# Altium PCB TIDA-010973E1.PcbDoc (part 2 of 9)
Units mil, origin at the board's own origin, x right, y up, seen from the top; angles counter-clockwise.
Board outline 5166 x 3669 mil, 8 copper layers (L01 - TOP, L02 - GND, L03 - SIG, L04 - GND, L05 - PWR, L06 - SIG, L07 - GND, L08 - BOTTOM), stack 61.7 mil thick; 677 components, 493 nets, 2522 pads, 1424 vias.
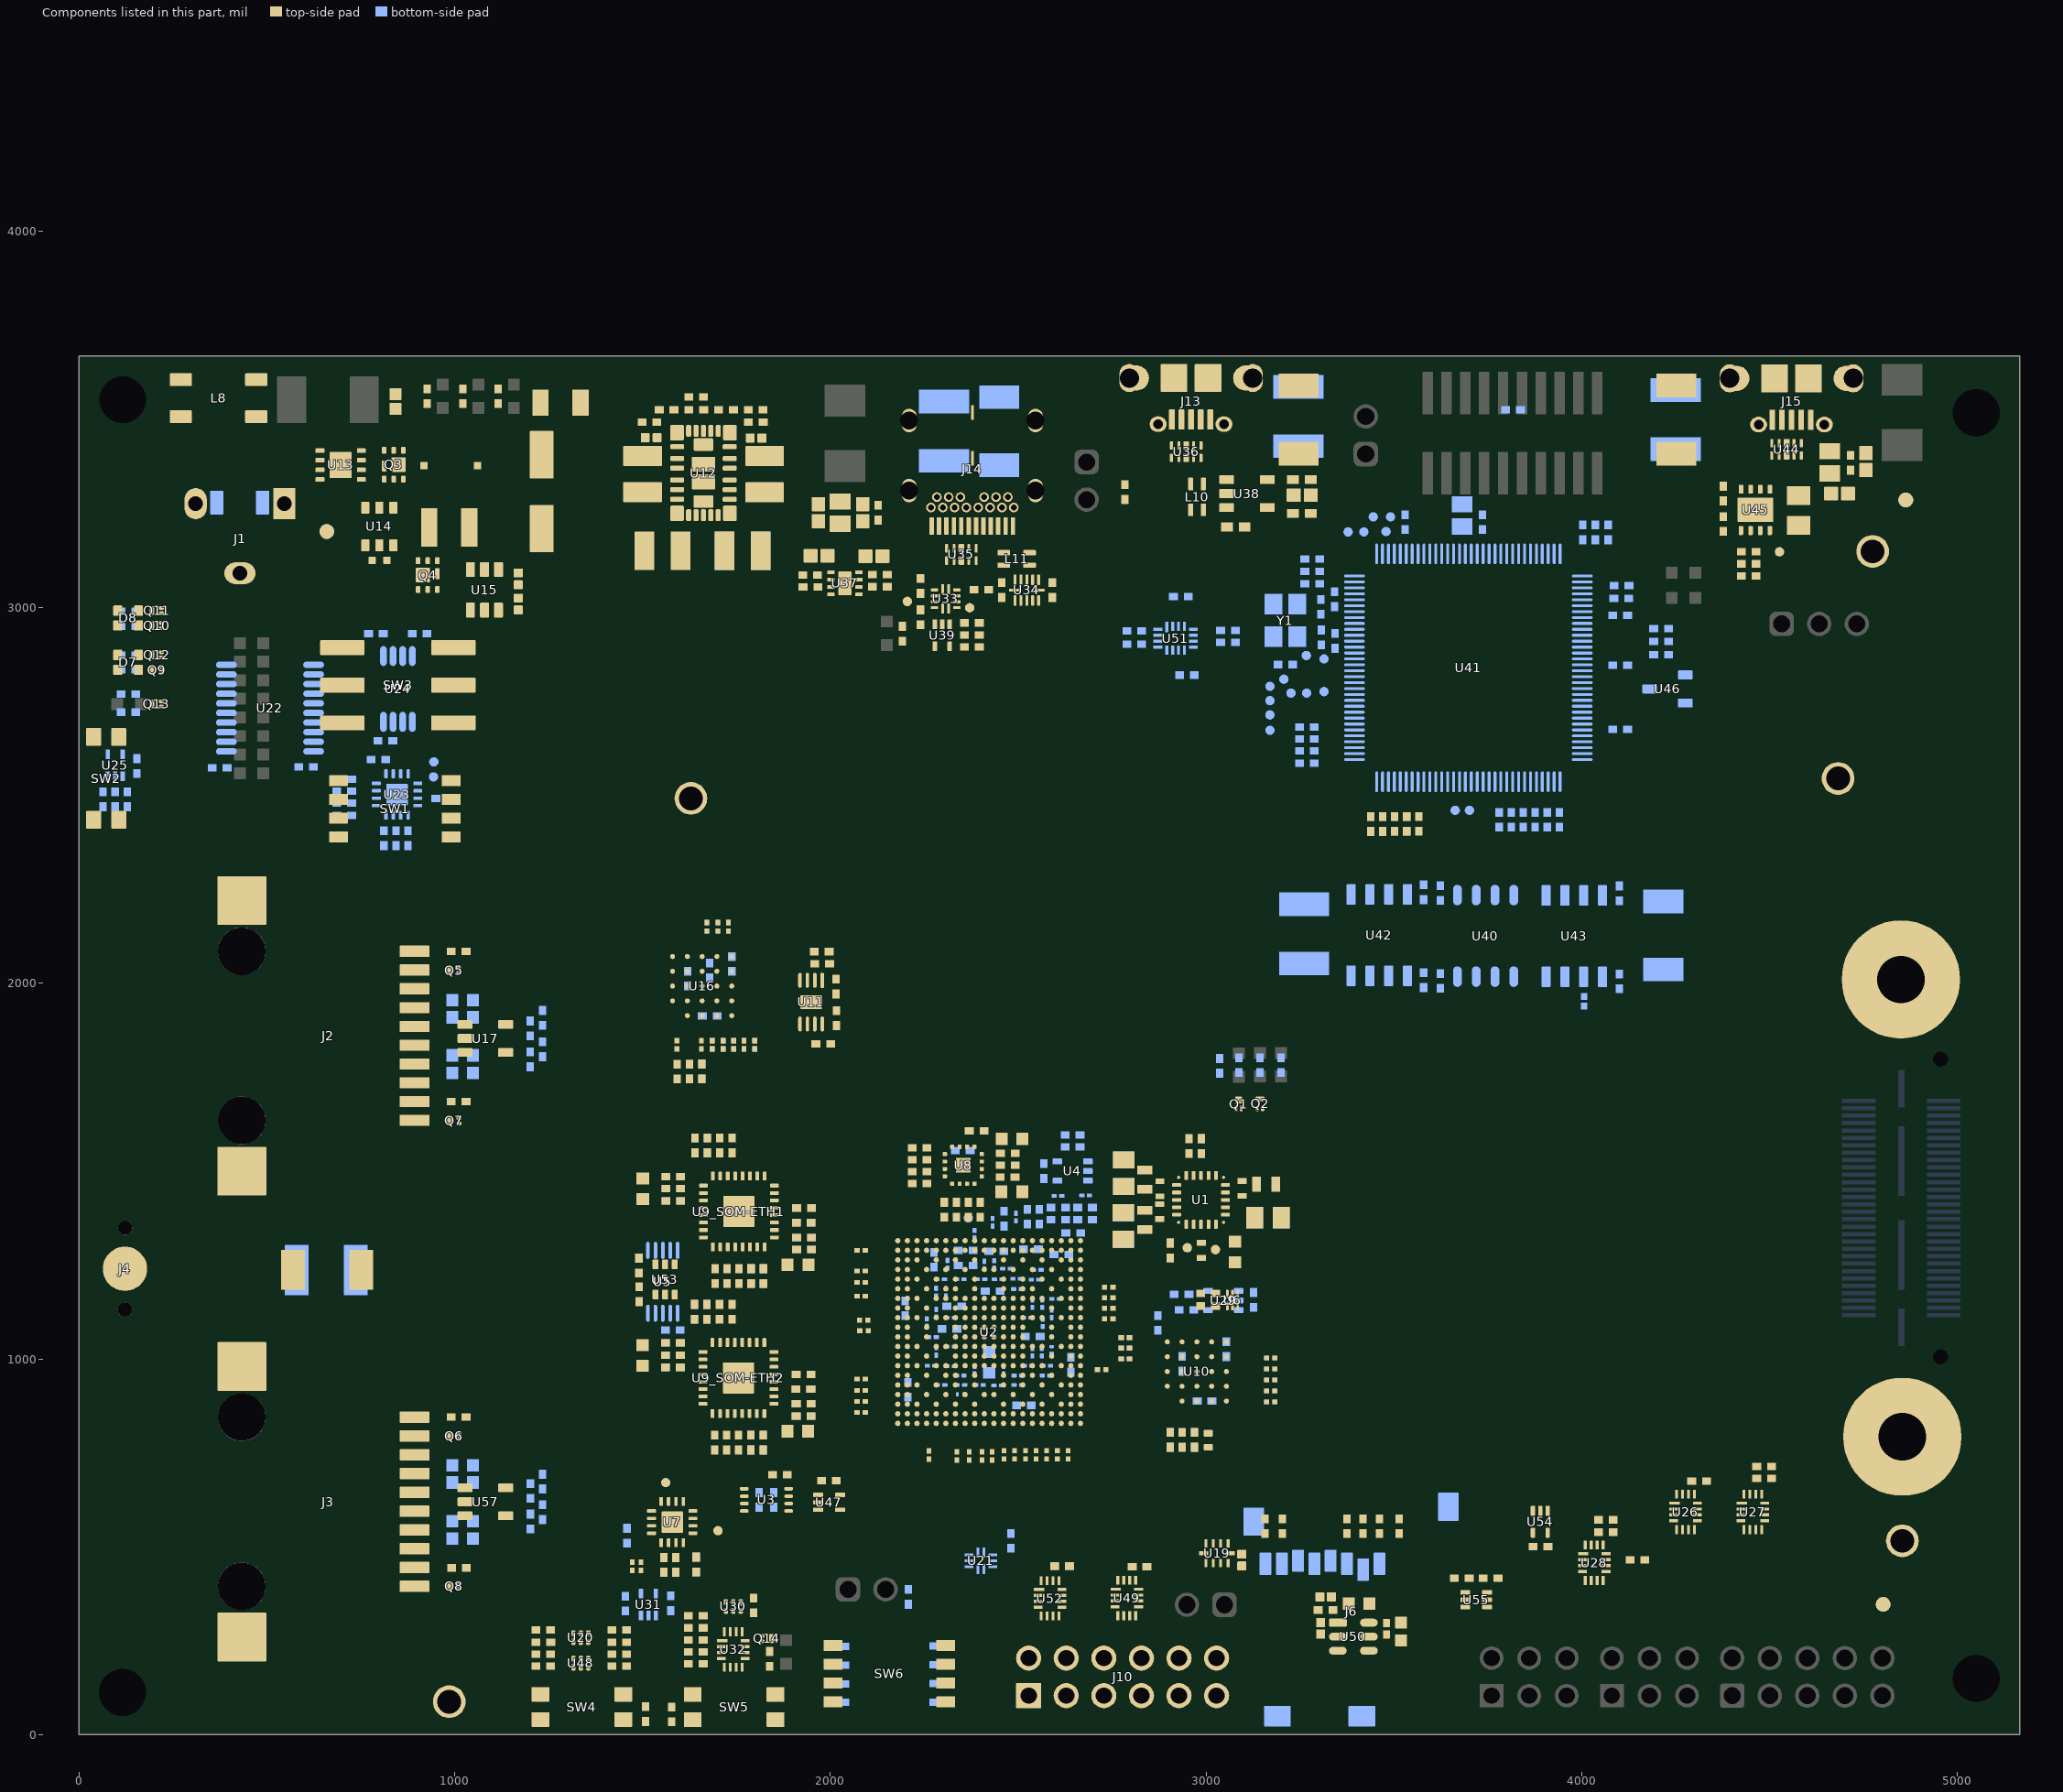
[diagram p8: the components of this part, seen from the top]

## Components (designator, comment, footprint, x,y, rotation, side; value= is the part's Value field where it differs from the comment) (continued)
L3 "74479262147" WE-PMCI_0603LP 2837.13,1477.54 r90 top value=470nH
L4_SOM-ETH1 "742792604" 0603L 1914.13,1250.64 r0 top value="22 ohm" (schematic designator L4)
L4_SOM-ETH2 "742792604" 0603L 1913.13,807.64 r0 top value="22 ohm" (schematic designator L4)
L5_SOM-ETH1 "742792604" 0603L 1501.26,1452.65 r90 top value="22 ohm" (schematic designator L5)
L5_SOM-ETH2 "742792604" 0603L 1500.26,1009.65 r90 top value="22 ohm" (schematic designator L5)
L6 "744031002" WE-TPC-S 990,3377 r0 top value=2.5uH
L7 "742792113" 1206L 1282,3545 r0 top value="120 ohm"
L8 "744212331" FP-744212331_SMT_CMC_6MM5_3MM6-MFG 372,3557 r0 top
L9 "74279206" 0805L 2026.32,3252 r270 top value="30 ohm"
L10 "744233900" FP-744233900_SMT4-MFG 2976,3294 r270 top
L11 "744233900" FP-744233900_SMT4-MFG 2496,3129 r0 top
L12 "74279206" 0805L 4660,3386 r90 top value="30 ohm"
L13 "74279271" 0402L 2442,1287 r0 bottom value="120 ohm"
L14 "74279271" 0402L 2606.68,1371 r0 bottom value="120 ohm"
L15 "74279271" 0402L 2678,1371 r180 bottom value="120 ohm"
L16 "74279266" 0603L 3407,349 r0 top value="1000 ohm"
L17 "742792604" 0603L 2484.02,1585.91 r180 top value="22 ohm"
L18 "742792604" 0603L 2483.04,1445.17 r180 top value="22 ohm"
LBL1 "THT-14-423-10" Label_650x200 4900,2571 r90 top
Logo1 "Texas Instruments" TI_Stacked_Overlay_Small 2537,2027 r0 top
Logo2 "CE Mark" CE_Mark_5mm 4507,905 r0 top
Logo3 "FCC disclaimer" FCC_disclaimer 5096,2357 r90 top
Logo4 "WEEE logo" WEEE_Minimum 5029,3267 r0 top
MH1 "MTG_NoPads" NPTH125mil 117,3553 r0 top
MH2 "MTG_NoPads" NPTH125mil 116,113 r0 top
MH3 "MTG_NoPads" NPTH125mil 5050,3518 r0 top
MH4 "MTG_NoPads" NPTH125mil 5050,150 r0 top
Q1 "BC847BFA-7B" FP-BC847BFA-7B_DFN3-MFG 3086.5,1679 r0 top value=45V
Q2 "CSD13383F4" YJC0003A 3143.5,1679 r90 top value=12V
Q3 "CSD19538Q2" DQK0006C 838.2,3380 r270 top value=100V
Q4 "CSD19538Q2" DQK0006C 928.8,3086 r90 top value=100V
Q5 "CSD13383F4" YJC0003A 998.23,2034 r180 top value=12V
Q6 "CSD13383F4" YJC0003A 998.23,795 r180 top value=12V
Q7 "CSD13383F4" YJC0003A 999,1634 r180 top value=12V
Q8 "CSD13383F4" YJC0003A 998.23,395 r180 top value=12V
Q9 "CSD13383F4" YJC0003A 207.21,2833.69 r180 top value=12V
Q10 "CSD13383F4" YJC0003A 207.21,2951.69 r180 top value=12V
Q11 "CSD13383F4" YJC0003A 207.21,2991.69 r180 top value=12V
Q12 "CSD13383F4" YJC0003A 207.21,2873.69 r180 top value=12V
Q13 "CSD13383F4" YJC0003A 207,2743 r180 top value=12V
Q14 "CSD13383F4" YJC0003A 1831,256 r0 top value=12V
R1 "CRCW040210K0FKED" 0402L 2556.15,1378.48 r90 bottom value=10.0k
R2 "CRCW04022K67FKED" 0402L 2524.15,1378.48 r270 bottom value=2.67k
R3 "CRCW0402180RJNED" 0402L 3200,1782 r90 bottom value=180
R4 "CRCW0402180RJNED" 0402L 3087,1782 r270 bottom value=180
R5 "CRCW0402180RJNED" 0402L 3143.5,1782 r270 bottom value=180
R6 "CRCW040210K0FKED" 0402L 1810.44,625 r270 bottom value=10.0k
R7 "CRCW040210K0FKED" 0402L 3005.68,1141 r180 top value=10.0k
R8 "CRCW040210K0FKED" 0402L 3126,1157 r270 bottom value=10.0k
R9 "CRCW040210K0FKED" 0402L 2645,1596 r180 bottom value=10.0k
R10 "CRCW040210K0FKED" 0402L 2568,1500 r270 bottom value=10.0k
R11 "CRCW04021K00FKED" 0402L 3036.5,1780 r90 bottom value=1.00k
R12 "CRCW040210K0FKED" 0402L 96.81,2489.22 r270 bottom value=10.0k
R13 "RC0201FR-074K7L" 0201L 2431,742 r270 top value=4.70k
R14 "CRCW040210K0FKED" 0402L 1849.81,625 r90 bottom value=10.0k
R15 "CRCW040210K0FKED" 0402L 1643,453 r90 top value=10.0k
R16 "CRCW020110K0FKED" 0201L 2741,1163 r180 top value=10.0k
R17 "RC0201FR-074K7L" 0201L 1496,448 r270 top value=4.70k
R18 "RMCF0402FT33R0" 0402L 2237.43,1466.72 r180 top value=33.0
R19 "RMCF0402FT33R0" 0402L 2237.43,1498.72 r180 top value=33.0
R20 "RMCF0402FT33R0" 0402L 2399.23,1397.18 r270 top value=33.0
R21 "CRCW040210K0FKED" 0402L 2352.37,1554.91 r0 bottom value=10.0k
R22 "CRCW04020000Z0ED" 0402L 2389.37,1606.91 r180 top value=0
R23_SOM-ETH1 "CRCW04022K20FKED" 0402L 1725.13,1220.64 r90 top value=2.20k (schematic designator R23)
R23_SOM-ETH2 "CRCW04022K20FKED" 0402L 1724.13,777.64 r90 top value=2.20k (schematic designator R23)
R24_SOM-ETH1 "CRCW040210K0FKED" 0402L 1640.13,1568.45 r270 top value=10.0k (schematic designator R24)
R24_SOM-ETH2 "CRCW040210K0FKED" 0402L 1639.13,1125.45 r270 top value=10.0k (schematic designator R24)
R25_SOM-ETH1 "CRCW040210K0FKED" 0402L 1640.13,1568.45 r270 bottom value=10.0k (schematic designator R25)
R25_SOM-ETH2 "CRCW040210K0FKED" 0402L 1639.13,1125.45 r270 bottom value=10.0k (schematic designator R25)
R26_SOM-ETH1 "CRCW04026K49FKED" 0402L 1693.13,1220.64 r90 top value=6.49k (schematic designator R26)
R26_SOM-ETH2 "CRCW04026K49FKED" 0402L 1692.13,777.64 r90 top value=6.49k (schematic designator R26)
R27_SOM-ETH1 "CRCW040210K0FKED" 0402L 1930.13,1401.64 r180 top value=10.0k (schematic designator R27)
R27_SOM-ETH2 "CRCW040210K0FKED" 0402L 1929.13,958.64 r180 top value=10.0k (schematic designator R27)
R28_SOM-ETH1 "CRCW04021K50FKED" 0402L 1673.13,1568.45 r90 bottom value=1.50k (schematic designator R28)
R28_SOM-ETH2 "CRCW04021K50FKED" 0402L 1672.13,1125.45 r90 bottom value=1.50k (schematic designator R28)
R29_SOM-ETH1 "CRCW04022K49FKED" 0402L 1706.13,1568.45 r270 top value=2.49k (schematic designator R29)
R29_SOM-ETH2 "CRCW04022K49FKED" 0402L 1705.13,1125.45 r270 top value=2.49k (schematic designator R29)
R30_SOM-ETH1 "CRCW04022K49FKED" 0402L 1739.13,1568.45 r270 top value=2.49k (schematic designator R30)
R30_SOM-ETH2 "CRCW04022K49FKED" 0402L 1738.13,1125.45 r270 top value=2.49k (schematic designator R30)
R31_SOM-ETH1 "CRCW04022K49FKED" 0402L 1789.13,1220.64 r90 top value=2.49k (schematic designator R31)
R31_SOM-ETH2 "CRCW04022K49FKED" 0402L 1788.13,777.64 r90 top value=2.49k (schematic designator R31)
R32_SOM-ETH1 "CRCW04022K49FKED" 0402L 1822.13,1220.64 r90 top value=2.49k (schematic designator R32)
R32_SOM-ETH2 "CRCW04022K49FKED" 0402L 1821.13,777.64 r90 top value=2.49k (schematic designator R32)
R33 "CRCW040210K0FKED" 0402L 2969.13,784.64 r270 top value=10.0k
R34 "CRCW040210K0FKED" 0402L 2936.8,784.64 r270 top value=10.0k
R35 "CRCW040210K0FKED" 0402L 2872,1096 r90 bottom value=10.0k
R36 "CRCW040210K0FKED" 0402L 2904.47,784.64 r270 top value=10.0k
R37 "RC0201FR-0749K9L" 0201L 3172.11,1002.64 r180 bottom value=49.9k
R38 "RC0201FR-0749K9L" 0201L 3172.11,914.89 r180 bottom value=49.9k
R39 "CRCW02014K70FKED" 0201_033L 2785,1000 r0 bottom value=4.70k
R40 "RC0201FR-0749K9L" 0201L 2784.98,1029 r0 bottom value=49.9k
R41 "RC0201FR-0749K9L" 0201L 2785,1057 r0 bottom value=49.9k
R42 "RC0201FR-0749K9L" 0201L 3172.11,973.39 r180 bottom value=49.9k
R43 "RC0201FR-0749K9L" 0201L 3172.11,944.14 r180 bottom value=49.9k
R44 "RC0201FR-0749K9L" 0201L 3172.11,885.64 r180 bottom value=49.9k
R45 "RC0201JR-0722RL" 0201L 3172.11,1002.64 r0 top value=22
R46 "RC0201JR-0722RL" 0201L 3172.11,914.89 r0 top value=22
R47 "RC0201JR-0722RL" 0201L 2785,1000 r180 top value=22
R48 "RC0201JR-0722RL" 0201L 2784.98,1029 r180 top value=22
R49 "RC0201JR-0722RL" 0201L 2785,1057 r180 top value=22
R50 "RC0201JR-0722RL" 0201L 3172.11,973.39 r0 top value=22
R51 "CRCW04021K00FKED" 0402L 2969.13,784.64 r90 bottom value=1.00k
R52 "CRCW0402100KFKED" 0402L 2904.47,784.64 r90 bottom value=100k
R53 "RC0201JR-0722RL" 0201L 3172.11,944.14 r0 top value=22
R54 "RC0201JR-0722RL" 0201L 3172.11,885.64 r0 top value=22
R55 "CRCW040210K0FKED" 0402L 2015.32,1991 r270 top value=10.0k
R56 "CRCW040210K0FKED" 0402L 1978.32,2052 r180 top value=10.0k
R57 "CRCW040210K0FKED" 0402L 1977.32,2084 r180 top value=10.0k
R58 "CRCW0402100KFKED" 0402L 1801.72,3492.65 r180 top value=100k
R59 "CRCW040235K7FKED" 0402L 1801.41,3525.65 r0 top value=35.7k
R60 "CRCW040240K2FKED" 0402L 1564.41,3525.65 r180 top value=40.2k
R61 "CRCW040213K0FKED" 0402L 1518.72,3492.65 r0 top value=13.0k
R62 "CRCW040210K0DHEDP" 0402L 1643.41,3525.65 r180 top value=10.0k
R63 "CRCW0402750RFKED" 0402L 1022,3562 r270 top value=750
R64 "CRCW04021K00FKED" 0402L 927,3562 r270 top value=1.00k
R65 "CRCW0402750RFKED" 0402L 1116,3562 r270 top value=750
R66 "RC0201FR-0749K9L" 0201L 1743,1836.02 r90 bottom value=49.9k
R67 "RC0201FR-0749K9L" 0201L 1685.67,1836 r90 bottom value=49.9k
R68 "CRCW02014K70FKED" 0201_033L 1672,2150 r270 bottom value=4.70k
R69 "RC0201FR-0749K9L" 0201L 1729,2150 r270 bottom value=49.9k
R70 "RC0201FR-0749K9L" 0201L 1700.5,2150 r270 bottom value=49.9k
R71 "RC0201FR-0749K9L" 0201L 1799,1836 r90 bottom value=49.9k
R72 "RC0201FR-0749K9L" 0201L 1770.67,1836 r90 bottom value=49.9k
R73 "RC0201FR-0749K9L" 0201L 1715,1836 r90 bottom value=49.9k
R74 "RC0201JR-0722RL" 0201L 1743,1836.02 r90 top value=22
R75 "RC0201JR-0722RL" 0201L 1685.67,1836 r90 top value=22
R76 "RC0201JR-0722RL" 0201L 1672,2150 r270 top value=22
R77 "RC0201JR-0722RL" 0201L 1729,2150 r270 top value=22
R78 "RC0201JR-0722RL" 0201L 1700.5,2150 r270 top value=22
R79 "RC0201JR-0722RL" 0201L 1799,1836 r90 top value=22
R80 "RC0201JR-0722RL" 0201L 1770.67,1836 r90 top value=22
R81 "RC0201JR-0722RL" 0201L 1715,1836 r90 top value=22
R82 "RC0201JR-0722RL" 0201L 1657.33,1836 r90 top value=22
R83 "CRCW02010000Z0ED" 0201L 1592,1836 r90 top value=0
R84 "CRCW0402220RJNTD" 0402L 1011,2085 r0 top value=220
R85 "CRCW0402220RJNTD" 0402L 1011,845 r0 top value=220
R86 "CRCW0402220RJNTD" 0402L 1011,1685 r0 top value=220
R87 "CRCW0402220RJNTD" 0402L 1012,444 r0 top value=220
R88 "CRCW20101M00FKEF" 2010 661,1237.68 r180 top value=1.00Meg
R89 "CRCW0402180RJNED" 0402L 132,2768.94 r0 bottom value=180
R90 "CRCW0402220RJNTD" 0402L 132,2950 r180 bottom value=220
R91 "CRCW0402180RJNED" 0402L 132,2990 r180 bottom value=180
R92 "CRCW0402220RJNTD" 0402L 132,2834 r180 bottom value=220
R93 "CRCW040210K0FKED" 0402L 2208,367 r90 bottom value=10.0k
R94 "CRCW0402180RJNED" 0402L 132,2873.37 r180 bottom value=180
R95 "CRCW040210K0FKED" 0402L 719,2695 r180 bottom value=10.0k
R96 "CRCW04022K67FKED" 0402L 375,2573 r0 bottom value=2.67k (schematic designator R?)
R98 "CRCW0402100RFKED" 0402L 64.81,2489.22 r90 bottom value=100
R99 "CRCW040210K0FKED" 0402L 1459,529.68 r90 bottom value=10.0k
R100 "CRCW040210K0FKED" 0402L 1643,453 r90 bottom value=10.0k
R103 "CRCW040210K0FKED" 0402L 812,2386 r90 bottom value=10.0k
R105 "CRCW040210K0FKED" 0402L 970,2492 r180 bottom value=10.0k
R107 "CRCW040210K0FKED" 0402L 706.31,2447 r0 bottom value=10.0k
R108 "CRCW0402100KFKED" 0402L 706.32,2479 r180 bottom value=100k
R109 "CRCW0402100KFKED" 0402L 706.32,2511 r180 bottom value=100k
R110 "CRCW0402100KFKED" 0402L 706.32,2543 r180 bottom value=100k
R111 "CRCW0402100KFKED" 0402L 797.32,2595 r180 bottom value=100k
R112 "CRCW0402100RFKED" 0402L 1508,55 r90 top value=100
R113 "CRCW0402100RFKED" 0402L 1578,54 r90 top value=100
R114 "CRCW040210K0FKED" 0402L 705,2891 r0 bottom value=10.0k
R115 "CRCW040210K0FKED" 0402L 996,2693 r180 bottom value=10.0k
R116 "CRCW040210K0FKED" 0402L 816,2645 r0 bottom value=10.0k
R117 "CRCW040210K0FKED" 0402L 790.68,2930 r0 bottom value=10.0k
R118 "CRCW040210K0FKED" 0402L 4485,714 r180 top value=10.0k
R119 "CRCW040210K0FKED" 0402L 4064,572 r180 top value=10.0k
R120 "CRCW020110K0FKED" 0201L 2741,1191 r180 top value=10.0k
R121 "CRCW020110K0FKED" 0201L 2337,742 r90 top value=10.0k
R122 "CRCW040249R9FKED" 0402L 1642.24,316.46 r0 top value=49.9
R123 "CRCW020110K0FKED" 0201L 2370,742 r90 top value=10.0k
R124 "CRCW040210K0FKED" 0402L 2018.78,235 r0 bottom value=10.0k
R125 "CRCW040210K0FKED" 0402L 2018.78,185.33 r0 bottom value=10.0k
R126 "CRCW040210K0FKED" 0402L 2018.78,135.67 r0 bottom value=10.0k
R127 "CRCW040210K0FKED" 0402L 2018.78,86 r0 bottom value=10.0k
R128 "CRCW04021K00FKED" 0402L 2295,236 r0 bottom value=1.00k
R129 "CRCW04021K00FKED" 0402L 2295,186 r0 bottom value=1.00k
R130 "CRCW04021K00FKED" 0402L 2295,136 r0 bottom value=1.00k
R131 "CRCW04021K00FKED" 0402L 2295,86 r0 bottom value=1.00k
R132 "CRCW0402110KFKED" 0402L 2784,3307 r270 top value=110k
R133 "CRCW040210K0FKED" 0402L 2456,3046 r90 top value=10.0k
R134 "CRCW040210K0FKED" 0402L 2591,3046 r90 top value=10.0k
R135 "CRCW0402200KFKED" 0402L 2240,2974 r270 top value=200k
R136 "CRCW040210K0FKED" 0402L 2377,2958.81 r0 top value=10.0k
R137 "CRCW040210K0FKED" 0402L 2377,2926.81 r0 top value=10.0k
R138 "CRCW0402909KFKED" 0402L 2240,3057 r90 top value=909k
R139 "CRCW20101M00FKEF" 2010 3246.32,3500 r90 top value=1.00Meg
R140 "CRCW040210K0FKED" 0402L 1947.33,3054.28 r0 top value=10.0k
R141 "CRCW040210K0FKED" 0402 3079,3214 r180 top value=10.0k
R142 "CRCW040210K0FKED" 0402 3255,3250 r0 top value=10.0k
R143 "CRCW0402715RFKED" 0402L 2192.28,2930 r90 top value=715
R144 "CRCW20101M00FKEF" 2010 2450,3469 r270 bottom value=1.00Meg
R145 "CRCW04020000Z0ED" 0402L 3282.67,3063.35 r180 bottom value=0
R146 "CRCW0402100RFKED" 0402L 3282.67,3095.85 r180 bottom value=100
R147 "CRCW0402330KFKED" 0402L 4070,3199.69 r90 bottom value=330k
R148 "CRCW0402330KFKED" 0402L 4036,3199.69 r270 bottom value=330k
R149 "CRCW0402360RJNED" 0402L 4105,3024 r180 bottom value=360
R150 "CRCW0402360RJNED" 0402L 4105.69,3058 r180 bottom value=360
R151 "CRCW04021K00FKED" 0402L 3812,2435 r90 bottom value=1.00k
R152 "CRCW04021K00FKED" 0402L 3780,2435 r90 bottom value=1.00k
R153 "CRCW20101M00FKEF" 2010 4251.31,3500 r90 top value=1.00Meg
R154 "CRCW04021K00FKED" 0402L 3438,2423.68 r90 bottom value=1.00k
R155 "CRCW04021K00FKED" 0402L 3470,2423.68 r90 bottom value=1.00k
R156 "CRCW04021K00FKED" 0402L 3502,2424 r90 bottom value=1.00k
R157 "CRCW04021K00FKED" 0402L 3534,2424 r90 bottom value=1.00k
R158 "CRCW04021K00FKED" 0402L 3534,2424 r90 top value=1.00k
R159 "CRCW04021K00FKED" 0402L 3502,2424 r90 top value=1.00k
R160 "CRCW04021K00FKED" 0402L 3470,2423.68 r90 top value=1.00k
R161 "CRCW04021K00FKED" 0402L 3438,2423.68 r90 top value=1.00k
R162 "CRCW20101M00FKEF" 2010 4217,2127 r90 bottom value=1.00Meg
R163 "CRCW040249R9FKED" 0402L 3268.31,2585 r0 bottom value=49.9
R164 "CRCW040210K0FKED" 0402L 3268.3,2681.7 r0 bottom value=10.0k
R165 "CRCW04021K00FKED" 0402L 4211,2943.55 r0 bottom value=1.00k
R166 "CRCW040251K1FKED" 0402L 4444,3116 r0 top value=51.1k
R167 "CRCW04024K87FKED" 0402L 3566,2424 r90 top value=4.87k
R168 "CRCW040230K0FKED" 0402L 4444,3084 r180 top value=30.0k
R169 "CRCW040210K0FKED" 0402L 1981.32,1839 r180 top value=10.0k
R171 "CRCW040210K0FKED" 0402L 1236.24,182.46 r180 top value=10.0k
R172 "CRCW040210K0FKED" 0402L 1642.24,188.65 r180 top value=10.0k
R173 "CRCW040210K0FKED" 0402L 1438.24,182.46 r0 top value=10.0k
R175 "CRCW040210K0FKED" 0402L 3461,555 r90 top value=10.0k
R176 "CRCW040210K0FKED" 0402L 3418,555 r90 top value=10.0k
R177 "CRCW040210K0FKED" 0402L 3375,555 r90 top value=10.0k
R178 "CRCW040210K0FKED" 0402L 3203,555 r90 top value=10.0k
R179 "CRCW040210K0FKED" 0402L 3157,555 r90 top value=10.0k
R180 "CRCW040210K0FKED" 0402L 2617,449 r180 bottom value=10.0k
R181 "CRCW040210K0FKED" 0402L 1455,349 r270 bottom value=10.0k
R182 "CRCW02010000Z0ED" 0201L 2741,1135 r180 top value=0
R183 "RC0201JR-0722RL" 0201L 2490.58,745 r270 top value=22
R184 "CRCW02010000Z0ED" 0201L 2741,1107 r180 top value=0
R185 "CRCW02010000Z0ED" 0201L 2082,1289 r0 top value=0
R186 "CRCW04020000Z0ED" 0402L 3817,3526 r0 bottom value=0
R187 "CRCW040210K0FKED" 0402L 1658,1765 r270 top value=10.0k
R188 "CRCW040210K0FKED" 0402L 1592,1764.69 r270 top value=10.0k
R189 "CRCW040210K0FKED" 0402L 1625,1764.69 r270 top value=10.0k
R190 "CRCW04021K00FKED" 0402L 1658,1765 r90 bottom value=1.00k
R191 "CRCW0402100KFKED" 0402L 1625,1764.69 r90 bottom value=100k
R192 "CRCW040210K0FKED" 0402L 2809,2937 r180 bottom value=10.0k
R193 "CRCW040210K0FKED" 0402L 2948,1131 r0 bottom value=10.0k
R194 "CRCW04021K00FKED" 0402L 2905.13,1288.95 r90 top value=1.00k
R195 "CRCW04021K00FKED" 0402L 2905.13,1288.95 r270 bottom value=1.00k
R196 "CRCW04021K00FKED" 0402L 2987.13,1566.61 r90 top value=1.00k
R197 "CRCW04021K00FKED" 0402L 2987.13,1566.61 r90 bottom value=1.00k
R198 "RMCF0402FT33R0" 0402L 2367.23,1397.18 r270 top value=33.0
R199 "CRCW04020000Z0ED" 0402L 2237.72,1530.42 r180 top value=0
R200 "CRCW04020000Z0ED" 0402L 2303.37,1397.23 r270 top value=0
R201_SOM-ETH1 "CRCW04022K49FKED" 0402L 1673.13,1568.45 r270 top value=2.49k (schematic designator R201)
R201_SOM-ETH2 "CRCW04022K49FKED" 0402L 1672.13,1125.45 r270 top value=2.49k (schematic designator R201)
R202 "CRCW04021K00FKED" 0402L 2955,1566.65 r270 top value=1.00k
R204_SOM-ETH1 "CRCW04021K50FKED" 0402L 1822.13,1220.64 r270 bottom value=1.50k (schematic designator R204)
R204_SOM-ETH2 "CRCW04021K50FKED" 0402L 1821.13,777.64 r270 bottom value=1.50k (schematic designator R204)
R205_SOM-ETH1 "CRCW04021K50FKED" 0402L 1789.13,1220.64 r270 bottom value=1.50k (schematic designator R205)
R205_SOM-ETH2 "CRCW04021K50FKED" 0402L 1788.13,777.64 r270 bottom value=1.50k (schematic designator R205)
R206_SOM-ETH1 "CRCW04021K50FKED" 0402L 1929.42,1362.64 r0 bottom value=1.50k (schematic designator R206)
R206_SOM-ETH2 "CRCW04021K50FKED" 0402L 1928.42,919.64 r0 bottom value=1.50k (schematic designator R206)
R207_SOM-ETH1 "CRCW04022K49FKED" 0402L 1929.42,1362.64 r180 top value=2.49k (schematic designator R207)
R207_SOM-ETH2 "CRCW04022K49FKED" 0402L 1928.42,919.64 r180 top value=2.49k (schematic designator R207)
R208 "CRCW02010000Z0ED" 0201L 2082,1167 r180 top value=0
R209 "CRCW02010000Z0ED" 0201L 2082,1204 r180 top value=0
R210 "CRCW02010000Z0ED" 0201L 2089.98,1075 r180 top value=0
R211 "CRCW02010000Z0ED" 0201L 2089,1103 r180 top value=0
R212 "RC0201JR-0722RL" 0201L 2722.34,971.66 r180 top value=22
R213 "CRCW040210K0FKED" 0402L 132,2721.22 r180 bottom value=10.0k
R214 "CRCW040210K0FKED" 0402L 1438.24,278.46 r180 top value=10.0k
R215 "CRCW04020000Z0ED" 0402L 1438.24,246.46 r0 top value=0
R216 "CRCW0402150RFKED" 0402L 1839,202 r90 top value=150
R217 "RC0201FR-074K7L" 0201L 2404,742 r270 top value=4.70k
R218 "RC0201FR-0733RL" 0201L 2462.1,745 r90 top value=33.0
R219 "RC0201FR-074K7L" 0201L 1473,448 r270 top value=4.70k
R220 "CRCW040210K0FKED" 0402L 4148,465 r0 top value=10.0k
R221 "CRCW040210K0FKED" 0402L 3514,555 r90 top value=10.0k
R222 "CRCW04020000Z0EDC" FP-CRCW04020000Z0EDC_0402-IPC_C 3480,282 r90 top value=0
R223 "RMCF0402FT33R0" 0402L 3940,2434.81 r90 bottom value=33.0
R224 "RMCF0402FT33R0" 0402L 3908,2434.81 r90 bottom value=33.0
R225 "RMCF0402FT33R0" 0402L 3876,2434.81 r90 bottom value=33.0
R226 "RC0201JR-0722RL" 0201 4006,1952 r90 bottom value=22
R227 "RC0201JR-0722RL" 0201L 2520,745 r270 top value=22
R228 "RC0201JR-0722RL" 0201L 2548,745 r270 top value=22
R229 "RC0201JR-0722RL" 0201L 2576.03,745 r270 top value=22
R230 "RC0201JR-0722RL" 0201L 2604.52,745 r270 top value=22
R231 "RC0201JR-0722RL" 0201L 2633,745 r270 top value=22
R232 "CRCW02010000Z0ED" 0201L 2082,1234 r0 top value=0
R233_SOM-ETH1 "CRCW04022K20FKED" 0402L 1757.13,1220.64 r90 top value=2.20k (schematic designator R233)
R233_SOM-ETH2 "CRCW04022K20FKED" 0402L 1756.13,777.64 r90 top value=2.20k (schematic designator R233)
R234 "CRCW02010000Z0ED" 0201L 2082,947 r180 top value=0
R235 "CRCW02010000Z0ED" 0201L 2082,916 r180 top value=0
R236 "CRCW02010000Z0ED" 0201L 2082,887 r180 top value=0
R237 "CRCW02010000Z0ED" 0201L 2082,858 r180 top value=0
R238 "CRCW02010000Z0ED" 0201L 2262.72,744.64 r270 top value=0
R239 "CRCW040210K0FKED" 0402L 2933,3029 r0 bottom value=10.0k
R240 "CRCW040210K0FKED" 0402L 3058.31,2939 r0 bottom value=10.0k
R241 "CRCW040210K0FKED" 0402L 3058.31,2907 r0 bottom value=10.0k
R242 "CRCW040210K0FKED" 0402L 2949,2820 r0 bottom value=10.0k
SH-J1 "60900213421" Wurth_60900213421 2020,4460 r90 top
SH-J2 "60900213421" Wurth_60900213421 4678,2733 r0 top
SW1 "416131160804" FP-416131160804_SMT_SW-MFG 841,2464 r90 top
SW2 "434351045816" FP-434351045816_SMT_SW_4MM7_4MM5-MFG 73,2545 r270 top
SW3 "428542320816" FP-428542320816_SMT_SW_7MM4_7MM4-MFG 849.32,2793 r0 top
SW4 "434351045816" FP-434351045816_SMT_SW_4MM7_4MM5-MFG 1339,74 r0 top
SW5 "434351045816" FP-434351045816_SMT_SW_4MM7_4MM5-MFG 1744,74 r0 top
SW6 "416131160804" FP-416131160804_SMT_SW-MFG 2157.36,162.57 r90 top
TP1 "TESTPOINT" TP_25MIL-SMT 2367.23,1375.53 r270 bottom
TP2 "5011" Keystone5011 4682,2545 r0 top
TP3 "5011" Keystone5011 4853,516 r0 top
TP4 "5011" Keystone5011 986,88 r0 top
TP5 "5011" Keystone5011 1629,2492 r0 top
TP6 "TESTPOINT" TP_25MIL-SMT 1701,543 r270 top
TP7 "TESTPOINT" TP_25MIL-SMT 945,2589 r90 bottom
TP8 "TESTPOINT" TP_25MIL-SMT 2371,2999 r0 top
TP9 "TESTPOINT" TP_25MIL-SMT 2205,3016 r0 top
TP10 "TESTPOINT" TP_25MIL-SMT 3491,3241 r90 bottom
TP11 "TESTPOINT" TP_25MIL-SMT 3479,3202 r90 bottom
TP12 "TESTPOINT" TP_25MIL-SMT 3445,3241 r90 bottom
TP13 "TESTPOINT" TP_25MIL-SMT 3420,3201 r90 bottom
TP14 "TESTPOINT" TP_25MIL-SMT 3378,3201 r90 bottom
TP15 "TESTPOINT" TP_25MIL-SMT 3701,2460 r90 bottom
TP16 "TESTPOINT" TP_25MIL-SMT 3663,2460 r90 bottom
TP17 "TESTPOINT" TP_25MIL-SMT 3267,2872 r90 bottom
TP18 "TESTPOINT" TP_25MIL-SMT 3314,2863 r90 bottom
TP19 "TESTPOINT" TP_25MIL-SMT 3207,2809 r90 bottom
TP20 "TESTPOINT" TP_25MIL-SMT 3226,2772 r90 bottom
TP21 "TESTPOINT" TP_25MIL-SMT 3314,2776 r90 bottom
TP22 "TESTPOINT" TP_25MIL-SMT 3267.68,2772 r90 bottom
TP23 "TESTPOINT" TP_25MIL-SMT 3170,2790 r90 bottom
TP24 "TESTPOINT" TP_25MIL-SMT 3170,2752 r90 bottom
TP25 "TESTPOINT" TP_25MIL-SMT 3170,2714 r90 bottom
TP26 "TESTPOINT" TP_25MIL-SMT 3170,2673 r90 bottom
TP27 "TESTPOINT" TP_25MIL-SMT 4526,3148 r0 top
TP29 "TESTPOINT" TP_25MIL-SMT 1562,671 r270 top
TP30 "TESTPOINT" TP_25MIL-SMT 944,2549 r90 bottom
TP31 "5011" Keystone5011 4774,3149 r0 top
TP32 "TESTPOINT" TP_25MIL-SMT 3025.13,1290.95 r180 top
TP33 "TESTPOINT" TP_25MIL-SMT 2950.13,1295.95 r180 top
U1 "TPS65214" VAF0024A-MFG 2986.76,1423.42 r90 top
U2 "AM2612AOFFHIZFGR" ZFG0304A-MFG 2422.75,1071.61 r180 top
U3 "SN74LVC2G08DCUR" DCU0008A_L 1830.13,625 r0 top
U4 "SN74AHC1G09DCKR" DCK0005A_L 2645,1500 r180 bottom
U5 "TS5A23159DGSR" DGS0010A_L 1554.32,1205.34 r270 bottom
U6 "SN74LVC1G125DSFR" DSF0006A 3070.5,1156.54 r90 top
U7 "TCA6408ARGTR" RGT0016A#1 1579.47,565.88 r180 top
U8 "LMK3C0105V33RERR" RER0016A-MFG 2354.02,1515.57 r270 top
U9_SOM-ETH1 "DP83826A" RHB0032M-MFG 1756.65,1392.48 r0 top (schematic designator U9)
U9_SOM-ETH2 "DP83826A" RHB0032M-MFG 1755.65,949.48 r0 top (schematic designator U9)
U10 "MX25UW6445GXDQ00" FP-MX25UW6445GXDQ00_BGA24-IPC_C 2975.56,966.69 r90 top
U11 "CAT24M01HU5I-GT3" FP-CAT24M01HU5I-GT3_UDFN8-IPC_A 1948.98,1949.5 r270 top
U12 "TLVM13630RDHR" RDH0030A-MFG 1662.41,3357.65 r0 top
U13 "TVS3301DRBT" DRB0008A 697,3379 r180 top
U14 "LM74700QDBVRQ1" DBV0006A_L 800,3215.31 r90 top
U15 "LM74700QDBVRQ1" DBV0006A_N 1079.68,3047 r270 top
U16 "APS12808L-OBMX-BA" FP-APS12808L-OBMX-BA_BGA24-IPC_C 1659,1992.37 r90 top
U17 "ESDS314DBVR" DBV0005A_N 1082,1853 r0 top
U19 "TPD6E001RSER" RSE0010A 3029,483 r270 top
U20 "SN74LVC1G07DRYR" DRY0006A 1336.24,258.46 r90 top
U21 "TMUX121NKGR" NKG0010A-MFG 2401,463 r90 bottom
U22 "TLC59108IPWR" PW0020A_N 508.94,2732.04 r0 bottom
U23 "TCA6408ARGTR" RGT0016A#2 847.12,2502.16 r0 bottom
U24 "PCA9536DGKR" DGK0008A_N 849.32,2783 r90 bottom
U25 "SN74LVC1G17DRLR" DRL0005A 97,2580 r90 bottom
U26 "TMUX1574RSVR" RSV0016A 4276,593 r0 top
U27 "TMUX1574RSVR" RSV0016A 4455,593 r0 top
U28 "TMUX1574RSVR" RSV0016A 4033,458 r0 top
U29 "SN74AHC1G09DCKR" DCK0005A_L 3046,1156 r180 bottom
U30 "SN74LVC1G17DRYR" DRY0006A 1741.86,341.46 r270 top
U31 "SN74LVC1G08DRLR" DRL0005A 1516.16,346.61 r90 bottom
U32 "SN74AVC4T245RSVR" RSV0016A 1741.87,226.65 r0 top
U33 "TUSB320LIRWBR" RWB0012A 2307,3023 r270 top
U34 "TS3USBA225RUTR" RUT0012A 2523,3046 r270 top
U35 "TPD4E02B04DQAR" DQA0010A 2349,3141 r270 top
U36 "TPD4E02B04DQAR" DQA0010A 2947.32,3414.56 r90 top
U37 "TPS22965TDSGRQ1" DSG0008B 2039,3064.28 r0 top
U38 "TPS2051BDBVR" DBV0005A_N 3109,3303 r0 top
U39 "SN74AHC1G02DRLR" DRL0005A 2298,2926 r270 top
U40 "ISO7220CDR" D0008B_N 3744,2126 r270 bottom
U41 "TM4C1294NCPDTT3" PDT0128A 3698.01,2839.3 r180 bottom
U42 "ISO7721DR" D0008B_HV 3461,2128.17 r90 bottom
U43 "ISO7721DR" D0008B_HV 3980,2125.17 r90 bottom
U44 "TPD4E02B04DQAR" DQA0010A 4545,3421 r90 top
U45 "TPS79601DRBR" DRB0008B 4462,3259.64 r270 top
U46 "LM4040C25QDBZR" DBZ0003A_N 4228,2783 r180 bottom
U47 "SN74AHC1G08DRLR" DRL0005A 1996.91,618.44 r0 top
U48 "SN74LVC2G17DRYR" DRY0006A 1336.24,190.46 r90 top
U49 "TMUX1574RSVR" RSV0016A 2789,364 r0 top
U50 "TPS22918DBVR" DBV0006A-IPC_C 3392,261 r0 top
U51 "TMUX1574RSVR" RSV0016A 2919,2918 r270 bottom
U52 "TMUX1574RSVR" RSV0016A 2585,363 r0 top
U53 "TXS0101DCKR" DCK0006A_L 1560.61,1211.51 r90 top
U54 "SN74AHC1G04DRLR" DRL0005A 3889.71,566.75 r270 top
U55 "SN74AXC1T45DRLR" DRL0006A 3718.89,359.32 r0 top
U57 "ESDS314DBVR" DBV0005A_N 1082,620 r0 top
Y1 "NX3225GA-16.000M-STD-CRG-1" NDK_NX3225GA 3211.01,2965.3 r0 bottom
ZZ1 "This Assembly Note is for PCB labels only" AssemblyNoteLabel 219,4557 r0 top
ZZ2 "These assemblies are ESD sensitive, ESD precautions shall be observed." AssemblyNote 193,4451 r0 top
ZZ3 "These assemblies must be clean and free from flux and all contaminants. Use of no clean flux is not acceptable." AssemblyNote 175,4286 r0 top
ZZ4 "These assemblies must comply with workmanship standards IPC-A-610 Class 2, unless otherwise specified." AssemblyNote 184,4365 r0 top

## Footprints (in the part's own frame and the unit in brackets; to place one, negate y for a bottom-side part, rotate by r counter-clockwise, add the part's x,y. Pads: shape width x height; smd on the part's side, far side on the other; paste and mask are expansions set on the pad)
0201 [mm] "Data from Kemet datasheet CC101_COM dated 7/28/11"
  rect 0.46x0.42 smd mask+0.048: 1(-0.33,0) 2(0.33,0)
  body extent -0.31,-0.16 0.31,0.16, height 0.26
0201_033L [mm] "0201"
  rect 0.36x0.32 smd mask+0.048: 1(-0.28,0) 2(0.28,0)
  body extent -0.31,-0.16 0.31,0.16, height 0.33
0201L [mm] "Data from Kemet datasheet CC101_COM dated 7/28/11"
  rect 0.36x0.32 smd mask+0.048: 1(-0.28,0) 2(0.28,0)
  body extent -0.31,-0.16 0.31,0.16, height 0.26
0402 [mm] "0402 from SM-752 data"
  rect 0.8x0.6 smd: 1(-0.6,0) 2(0.6,0)
  silkscreen extent -1.22,-0.52 1.22,0.52, body extent -0.55,-0.3 0.55,0.3, height 0.6
0402_065S [mil] "Based on C0402S footprint from PADS legacy"
  rect 15x24 smd: 1(-20,0) 2(20,0)
  body extent -22,-12 22,12, height 26
0402L [mm] "0402 from SM-752 data"
  rect 0.6x0.5 smd: 1(-0.5,0) 2(0.5,0)
  body extent -0.55,-0.3 0.55,0.3, height 0.6
0603L [mm] "0603 from SM-752 data"
  rect 0.8x0.85 smd: 1(-0.7,0) 2(0.7,0)
  silkscreen extent -0.07,-0.33 0.07,0.33, body extent -0.87,-0.47 0.87,0.47, height 1
0805_150 [mm] "0805 / 1.5 mm height"
  rect 1.15x1.45 smd: 1(-0.9,0) 2(0.9,0)
  silkscreen extent -0.1,-0.8 0.1,0.8, body extent -1.1,-0.72 1.1,0.72, height 1.5
0805_HV [mil] "0805 with 30mil clearance between pads"
  rect 50x63 smd: 1(-40,0) 2(40,0)
  silkscreen extent -74,-40 74,40, body extent -43,-29 43,29, height 57
0805L [mm] "0805 from SM-752 data"
  rect 1.1x1.4 smd: 1(-0.75,0) 2(0.75,0)
  body extent -1.1,-0.72 1.1,0.72, height 1.45
1206L [mm] "1206 from SM-752 data"
  rect 1.1x1.75 smd: 1(-1.35,0) 2(1.35,0)
  silkscreen extent -0.4,-0.77 0.4,0.77, body extent -1.7,-0.9 1.7,0.9, height 1.35
1210_270L [mm] "1210"
  rect 1.1x2.6 smd: 1(-1.35,0) 2(1.35,0)
  silkscreen extent -0.4,-1.2 0.4,1.2, body extent -1.7,-1.35 1.7,1.35, height 2.7
1812_254 [mm] "SMD, 2-Leads, Body 4.8x3.4mm"
  rect 1.6x3.4 smd: 1(-2,0) 2(2,0)
  silkscreen extent -0.8,-1.7 0.8,1.7, body extent -2.4,-1.7 2.4,1.7, height 2.54
2010 [mm] "Chip Capacitor, Body 5.08x2.54mm, IPC Medium Density"
  rect 1.6x2.7 smd: 1(-2.3,0) 2(2.3,0)
  silkscreen extent -3.42,-1.65 3.42,1.65, body extent -2.73,-1.45 2.73,1.45, height 1.66
AssemblyNote [mil] "Assembly Note"
AssemblyNoteLabel [mil] "Assembly Note for PCB Labels"
CE_Mark_5mm [mil] "Minimum text height for CE Mark"
  silkscreen extent -138,-98 138,98
CUI_PJ-102AH [mm] "DC POWER JACK, R/A, TH"
  rect 2.1x1.5 hole 1 slot 1.6 at 0 deg: 1(0,3)
  oval 2.1x1.5 hole 1 slot 1.6 at 0 deg: 2(0,-3)
  oval 1.5x2.1 hole 1 slot 1.6 at 90 deg: 3(4.7,0)
  silkscreen extent -4.5,-10.7 4.5,4.3, body extent -4.5,-10.7 4.9,3.7, height 11
D0008B_HV [mm] "SOIC, 8-Leads, Body 4.9x3.9mm, Pitch 1.27mm, HV / Isolation option"
  rrect17% 1.4x0.6 smd: 1(-2.75,1.905) 2(-2.75,0.635) 3(-2.75,-0.635) 4(-2.75,-1.905) 5(2.75,-1.905) 6(2.75,-0.635) 7(2.75,0.635) 8(2.75,1.905)
  silkscreen extent -3.3,-2.5 0.9,2.5, body extent -3,-2.45 3,2.45, height 1.63
D0008B_N [mil] "SOIC, 8-Leads, Body 4.9x3.9mm, Pitch 1.27mm, IPC Medium Density"
  oval 55x23.62 smd: 1(-108.5,75) 2(-108.5,25) 3(-108.5,-25) 4(-108.5,-75) 5(108.5,-75) 6(108.5,-25) 7(108.5,25) 8(108.5,75)
  silkscreen extent -130,-98 35,98, body extent -118,-96 118,96, height 64
DBV0005A_N [mm] "SOT23, 5-Leads, Body 2.9x1.6mm, Pitch 0.95mm, Lead Span 2.8mm, IPC Medium Density"
  rrect17% 1x0.6 smd: 1(-1.375,0.95) 2(-1.375,0) 3(-1.375,-0.95) 4(1.375,-0.95) 5(1.375,0.95)
  silkscreen extent -1.63,-1.55 0.38,1.55, body extent -1.42,-1.46 1.42,1.46, height 1.09
DBV0006A-IPC_C [mm]
  rrect19% 1.205x0.53 smd paste+0 mask+0: 1(-1.05,0.95)
  rrect100% 1.205x0.53 smd paste+0 mask+0: 2(-1.05,0) 3(-1.05,-0.95) 4(1.05,-0.95) 5(1.05,0) 6(1.05,0.95)
  silkscreen extent -0.4,-1.45 0.05,1.6, body extent -1.75,-1.55 1.75,1.55, height 0.25
DBV0006A_L [mm] "SOT23, 6-Leads, Body 2.9x1.6mm, Pitch 0.95mm, Lead Span 2.8mm, IPC High Density"
  rrect18% 0.8x0.55 smd: 1(-1.275,0.95) 2(-1.275,0) 3(-1.275,-0.95) 4(1.275,-0.95) 5(1.275,0) 6(1.275,0.95)
  silkscreen extent -1.55,-1.53 0.55,1.53, body extent -1.42,-1.46 1.42,1.46, height 1.12
DBV0006A_N [mm] "SOT23, 6-Leads, Body 2.9x1.6mm, Pitch 0.95mm, Lead Span 2.8mm, IPC Medium Density"
  rrect17% 1x0.6 smd: 1(-1.375,0.95) 2(-1.375,0) 3(-1.375,-0.95) 4(1.375,-0.95) 5(1.375,0) 6(1.375,0.95)
  silkscreen extent -1.68,-1.55 0.5,1.55, body extent -1.42,-1.46 1.42,1.46, height 1.12
DBZ0003A_N [mm] "SOT23, 3-Leads, Body 2.9x1.3mm, Pitch 0.95mm, Lead Span 2.4mm, IPC Medium Density"
  rrect17% 1x0.6 smd: 1(-1.2,0.95) 2(-1.2,-0.95) 3(1.2,0)
  silkscreen extent 0.2,-1.5 0.7,1.5, body extent -1.26,-1.46 1.26,1.46, height 0.98
DCK0005A_L [mm] "SOT353, 5-Leads, Body 2x1.3mm, Pitch 0.65mm, Lead Span 2.1mm, IPC High Density"
  rrect25% 0.65x0.4 smd: 1(-1.025,0.65) 2(-1.025,0) 3(-1.025,-0.65) 4(1.025,-0.65) 5(1.025,0.65)
  silkscreen extent -1.27,-1.09 0.56,1.09, body extent -1.14,-1 1.14,1, height 0.95
DCK0006A_L [mm] "SOT23, 6-Leads, Body 2x1.3mm, Pitch 0.65mm, Lead Span 2.1mm, IPC High Density"
  rrect25% 0.65x0.4 smd: 1(-1.025,0.65) 2(-1.025,0) 3(-1.025,-0.65) 4(1.025,-0.65) 5(1.025,0) 6(1.025,0.65)
  silkscreen extent -1.3,-1.07 0.55,1.1, body extent -1.14,-1 1.14,1, height 0.95
DCU0008A_L [mm] "TSSOP, 8-Leads, Body 2x2.3mm, Pitch 0.5mm, IPC High Density"
  oval 0.6x0.25 smd: 1(-1.5,0.75) 2(-1.5,0.25) 3(-1.5,-0.25) 4(-1.5,-0.75) 5(1.5,-0.75) 6(1.5,-0.25) 7(1.5,0.25) 8(1.5,0.75)
  silkscreen extent -1.05,-1.05 0.38,1.05, body extent -1.56,-1 1.56,1, height 0.9
DGK0008A_N [mm] "TSOP, 8-Leads, Body 3x3mm, Pitch 0.65mm, IPC Medium Density"
  oval 1.35x0.45 smd: 1(-2.225,0.975) 2(-2.225,0.325) 3(-2.225,-0.325) 4(-2.225,-0.975) 5(2.225,-0.975) 6(2.225,-0.325) 7(2.225,0.325) 8(2.225,0.975)
  silkscreen extent -2.75,-1.55 0.95,1.55, body extent -2.45,-1.5 2.45,1.5, height 0.96
DGS0010A_L [mm] "TSSOP, 10-Leads, Body 3x3mm, Pitch 0.5mm, IPC High Density"
  oval 1.15x0.25 smd: 1(-2.125,1) 2(-2.125,0.5) 3(-2.125,0) 4(-2.125,-0.5) 5(-2.125,-1) 6(2.125,-1) 7(2.125,-0.5) 8(2.125,0) 9(2.125,0.5) 10(2.125,1)
  silkscreen extent -2.65,-1.55 0.9,1.55, body extent -2.45,-1.5 2.45,1.5, height 0.96
DQA0010A [mm] "SON, 10-Leads, Body 1x2.5mm, Pitch 0.5mm, TI Recommended"
  rrect50% 0.565x0.2 smd: 1(-0.417,1) 2(-0.417,0.5) 4(-0.417,-0.5) 5(-0.417,-1) 6(0.417,-1) 7(0.417,-0.5) 9(0.417,0.5) 10(0.417,1)
  rrect28% 0.565x0.36 on Top Paste: 3(-0.417,0) 8(0.417,0)
  rrect25% 0.565x0.4 smd paste-0.2: 3(-0.417,0) 8(0.417,0)
  silkscreen extent -0.67,-1.45 0.55,1.45, body extent -0.55,-1.3 0.55,1.3, height 0.56
DQK0006C [mm] "WSON"
  rrect12% 0.9x0.86 on Top Paste: 0(0,0.325)
  rrect34% 0.7x0.29 on Top Paste: 0(0.095,-0.65)
  rrect33% 0.45x0.3 smd: 1(-0.975,0.65) 2(-0.975,0) 3(-0.975,-0.65) 4(0.975,-0.65) 5(0.975,0) 6(0.975,0.65)
  rrect33% 0.75x0.3 smd paste-0.15: 7(0.095,-0.65)
  rrect11% 1x0.95 smd paste-0.5: 8(0,0.325)
  silkscreen extent -1.15,-1.15 1.15,1.15, body extent -1,-1 1,1, height 0.82
DRB0008A [mm] "VSON-8"
  rrect32% 0.6x0.31 smd: 1(-1.4,0.975) 2(-1.4,0.325) 3(-1.4,-0.325) 4(-1.4,-0.975) 5(1.4,-0.975) 6(1.4,-0.325) 7(1.4,0.325) 8(1.4,0.975)
  rrect7% 1.5x1.75 smd paste-0.75: 9(0,0)
  L01 - TOP region: -0.7,-0.875 -0.49,-0.875 -0.471,-0.879 -0.455,-0.89 -0.444,-0.906 -0.44,-0.925 -0.44,-0.925 -0.44,-1.65 -0.436,-1.669 -0.425,-1.685 -0.409,-1.696 -0.39,-1.7 -0.39,-1.7 -0.26,-1.7 -0.241,-1.696 -0.225,-1.685 -0.214,-1.669 -0.21,-1.65 -0.21,-1.65 -0.21,-0.925 -0.206,-0.906 -0.195,-0.89 -0.179,-0.879 -0.16,-0.875 -0.16,-0.875 0.16,-0.875 0.179,-0.879 0.195,-0.89 0.206,-0.906 0.21,-0.925 0.21,-0.925 0.21,-1.65 0.21,-1.65 0.214,-1.669 0.225,-1.685 0.241,-1.696 0.26,-1.7 0.26,-1.7 0.39,-1.7 0.409,-1.696 0.425,-1.685 0.436,-1.669 0.44,-1.65 0.44,-1.65 0.44,-0.925 0.444,-0.906 0.455,-0.89 0.471,-0.879 0.49,-0.875 0.49,-0.875 0.7,-0.875 0.719,-0.871 0.735,-0.86 0.746,-0.844 0.75,-0.825 0.75,-0.825 0.75,0.825 0.746,0.844 0.735,0.86 0.719,0.871 0.7,0.875 0.7,0.875 0.49,0.875 0.471,0.879 0.455,0.89 0.444,0.906 0.44,0.925 0.44,0.925 0.44,1.65 0.436,1.669 0.425,1.685 0.409,1.696 0.39,1.7 0.39,1.7 0.26,1.7 0.241,1.696 0.225,1.685 0.214,1.669 0.21,1.65 0.21,1.65 0.21,1.65 0.21,0.925 0.206,0.906 0.195,0.89 0.179,0.879 0.16,0.875 0.16,0.875 -0.16,0.875 -0.179,0.879 -0.195,0.89 -0.206,0.906 -0.21,0.925 -0.21,0.925 -0.21,1.65 -0.214,1.669 -0.225,1.685 -0.241,1.696 -0.26,1.7 -0.26,1.7 -0.39,1.7 -0.409,1.696 -0.425,1.685 -0.436,1.669 -0.44,1.65 -0.44,1.65 -0.44,0.925 -0.444,0.906 -0.455,0.89 -0.471,0.879 -0.49,0.875 -0.49,0.875 -0.7,0.875 -0.719,0.871 -0.735,0.86 -0.746,0.844 -0.75,0.825 -0.75,0.825 -0.75,-0.825 -0.746,-0.844 -0.735,-0.86 -0.719,-0.871 -0.7,-0.875
  silkscreen extent -1.73,-1.73 1.73,1.73, body extent -1.5,-1.5 1.5,1.5, height 0.77
DRB0008B [mm] "SON, 8-Leads, Body 3x3mm, Pitch 0.65mm, Thermal Pad 2.4x1.65mm, TI Recommended"
  rrect33% 0.6x0.3 smd: 1(-1.4,0.975) 2(-1.4,0.325) 3(-1.4,-0.325) 4(-1.4,-0.975) 5(1.4,-0.975) 6(1.4,-0.325) 7(1.4,0.325) 8(1.4,0.975)
  rrect9% 1.47x1.06 on Top Paste: 9(0,0.63) 9(0,-0.63)
  rrect6% 1.65x2.4 smd paste-1.2: 9(0,0)
  silkscreen extent -1.73,-1.73 1.73,1.73, body extent -1.5,-1.5 1.5,1.5, height 0.96
DRL0005A [mm] "SOTFL, 5-Flat Leads, Body 1.2x1.6x0.6mm, Pitch 0.5mm, TI recommended"
  rrect33% 0.67x0.3 smd: 1(-0.74,0.5) 2(-0.74,0) 3(-0.74,-0.5) 4(0.74,-0.5) 5(0.74,0.5)
  silkscreen extent -0.9,-0.95 0.5,0.95, body extent -0.85,-0.85 0.85,0.85, height 0.62
DRL0006A [mm] "SOTFL, 6-Flat Leads, Body 1.2x1.6x0.6mm, Pitch 0.5mm, TI recommended"
  rrect33% 0.67x0.3 smd: 1(-0.74,0.5) 2(-0.74,0) 3(-0.74,-0.5) 4(0.74,-0.5) 5(0.74,0) 6(0.74,0.5)
  silkscreen extent -0.9,-0.95 0.5,0.95, body extent -0.8,-0.8 0.8,0.8, height 0.61
DRY0006A [mm] "USON-6"
  rrect67% 0.45x0.3 smd paste-0.05 mask-0.05: 1(-0.275,0.5)
  rrect67% 0.4x0.3 smd paste-0.05 mask-0.05: 2(-0.3,0) 3(-0.3,-0.5) 4(0.3,-0.5) 5(0.3,0) 6(0.3,0.5)
  body extent -0.5,-0.72 0.5,0.73, height 0.58
DSF0006A [mm] "TI recommended land pattern"
  rrect59% 0.6x0.17 smd mask+0.045: 1(-0.4,0.35) 2(-0.4,0) 3(-0.4,-0.35) 4(0.4,-0.35) 5(0.4,0) 6(0.4,0.35)
  silkscreen extent -0.6,-0.63 0.6,0.63, body extent -0.5,-0.5 0.5,0.5, height 0.48
DSG0008B [mm] "SON, 8-Leads, Body 2x2mm, Pitch 0.5mm, Thermal Pad 1.6x0.9mm, TI Recommended"
  rrect14% 0.9x0.7 on Top Paste: 0(0,-0.45) 0(0,0.45)
  rrect40% 0.5x0.25 smd: 1(-0.95,0.75) 2(-0.95,0.25) 3(-0.95,-0.25) 4(-0.95,-0.75) 5(0.95,-0.75) 6(0.95,-0.25) 7(0.95,0.25) 8(0.95,0.75)
  rrect11% 0.9x1.6 smd paste-0.45: 9(0,0)
  silkscreen extent -1.07,-1.15 1.07,1.15, body extent -1,-1 1,1, height 0.77
FCC_disclaimer [mil]
Fiducial10-20 [mm]
  round 1 smd mask+0.5: 1(0,0)
  L01 - TOP keep-out circle w1.178: c0,0 r0.5
FP-150066RG74000_0606-MFG [mm] "Recommended Land Pattern"
  rrect17% 0.6x0.7 smd paste+0 mask+0: 1(-0.7,0.5) 2(-0.7,-0.5) 3(0.7,-0.5) 4(0.7,0.5)
  silkscreen extent -1.54,-0.85 0,1.36, body extent -0.8,-0.8 0.8,0.8, height 0.8
FP-7466313R_SMT_REDCUBE_7MM00_4MM33-MFG [mm]
  round 0.97 hole 0.97 unplated paste-2539.97 mask+0: 1(-2.77,0) 1(2.77,0)
  round 2.997 smd paste-1000 mask+0: 1(0,0)
  L01 - TOP region: -3.079,-1.665 -3.5,0 -3.079,1.665 -3.079,1.665 3.079,1.665 3.5,0 3.079,-1.665 3.079,-1.665
  silkscreen extent -4,-2.22 4,2.21, body extent -4.1,-2.31 4.1,2.31, height 0.25
FP-744212331_SMT_CMC_6MM5_3MM6-MFG [mm] "Recommended Land Pattern"
  rrect12% 1.5x0.85 smd paste+0 mask+0: 1(2.55,1.25) 3(2.55,-1.25) 4(-2.55,-1.25) 5(-2.55,1.25)
  silkscreen extent -3.25,-1.88 3.98,1.88, body extent -2.6,-1.8 2.6,1.8, height 1.8
FP-744233900_SMT4-MFG [mm] "Recommended Land Pattern"
  rrect29% 0.85x0.35 smd paste+0 mask+0: 1(-0.875,0.425) 2(0.875,0.425) 3(0.875,-0.425) 4(-0.875,-0.425)
  silkscreen extent -1.97,-0.7 0.08,0.7, body extent -1,-0.6 1,0.6, height 1.4
FP-7498011211_RJ45MAG-MFG [mm] "Recommended Land Pattern"
  rrect13% 0.76x2.03 smd paste+0 mask+0: 1(-5.715,11.665) 2(-4.445,11.665) 3(-3.175,11.665) 4(-1.905,11.665) 5(-0.635,11.665) 6(0.635,11.665) 7(1.905,11.665) 8(3.175,11.665) 9(4.445,11.665) 10(5.715,11.665)
  rrect3% 3.3x3.3 smd paste+0 mask+0: 11(-9.145,-0.015) 12(9.145,-0.015)
  round 3.22 hole 3.22 unplated paste-2539.97 mask+0: ""(-5.715,-0.015) ""(5.715,-0.015)
  silkscreen extent -8.1,2.01 8.1,12.65, body extent -10.89,-11.05 10.89,12.78, height 0.25
FP-61301221121_HDR12-MFG [mm]
  rrect6% 1.7x1.7 hole 1.1 paste-2539.97 mask+0: 1(-6.35,-1.27)
  round 1.7 hole 1.1 paste-2539.97 mask+0: 2(-6.35,1.27) 3(-3.81,-1.27) 4(-3.81,1.27) 5(-1.27,-1.27) 6(-1.27,1.27) 7(1.27,-1.27) 8(1.27,1.27) 9(3.81,-1.27) 10(3.81,1.27) 11(6.35,-1.27) 12(6.35,1.27)
  silkscreen extent -7.77,-3.22 7.77,2.62, body extent -7.87,-2.72 7.87,2.72, height 0.25
FP-416131160804_SMT_SW-MFG [mm]
  rrect13% 0.76x1.27 smd paste+0 mask+0: 1(-1.905,-3.81) 2(-0.635,-3.81) 3(0.635,-3.81) 4(1.905,-3.81) 5(1.905,3.81) 6(0.635,3.81) 7(-0.635,3.81) 8(-1.905,3.81)
  silkscreen extent -3.27,-5.34 3.27,2.93, body extent -3.37,-4.54 3.37,4.54, height 0.25
FP-428542320816_SMT_SW_7MM4_7MM4-MFG [mm] "Recommended Land Pattern"
  rrect10% 3x1 smd paste+0 mask+0: 1(-3.75,2.54) 2(3.75,-2.54) 4(-3.75,-2.54) 8(3.75,2.54) C(-3.75,0) C(3.75,0)
  silkscreen extent -5.12,-3.8 3.8,3.8, body extent -5.35,-3.9 5.35,3.9, height 0.25
FP-434351045816_SMT_SW_4MM7_4MM5-MFG [mm]
  rrect10% 1.2x1 smd paste+0 mask+0: 1(2.8,0.85) 2(2.8,-0.85) 3(-2.8,0.85) 4(-2.8,-0.85)
  silkscreen extent -2.4,0.73 4.07,1.85, body extent -3.5,-2.95 3.5,1.95, height 0.25
FP-629105150921_CONN_PTH_USB_8MM0_5MM6-MFG [mm]
  rrect25% 0.4x1.35 smd paste+0 mask+0: 1(-1.3,2.335) 2(-0.65,2.335) 3(0,2.335) 4(0.65,2.335) 5(1.3,2.335)
  rrect100% 1.15x1.05 hole 0.65 slot 0.75 at 0 deg paste-2539.97 mask+0: 6(-2.225,2.65) 7(2.225,2.65)
  rrect100% 1.35x1.9 hole 1.3 slot 0.75 at 0 deg paste-2539.97 mask+0: 8(-4.175,-0.47) 11(4.173,-0.47)
  round 1.71 smd paste+0 mask+0: 8(-3.699,-0.47) 11(3.699,-0.47)
  rrect6% 1.8x1.9 smd paste+0 mask+0: 9(-1.15,-0.47) 10(1.15,-0.47)
  L01 - TOP region: 2.6,0.48 4.35,0.48 4.541,0.442 4.704,0.334 4.812,0.171 4.85,-0.02 4.85,-0.02 4.85,-0.92 4.812,-1.111 4.704,-1.274 4.541,-1.382 4.35,-1.42 4.35,-1.42 2.6,-1.42
  L01 - TOP region: -2.6,-1.42 -4.35,-1.42 -4.541,-1.382 -4.704,-1.274 -4.812,-1.111 -4.85,-0.92 -4.85,-0.92 -4.85,-0.02 -4.812,0.171 -4.704,0.334 -4.541,0.442 -4.35,0.48 -4.35,0.48 -2.6,0.48
  silkscreen extent -3.8,0.86 3.8,3.71, body extent -4.95,-2.7 4.95,3.27, height 0.25
FP-632723300011_CONN_USB_8MM74_11MM20-MFG [mm]
  round 0.65 hole 0.4 paste-2539.97 mask+0: 1(-2,4.68) 2(2,4.68) B1(2.8,4.68) B2(2.4,3.98) B3(1.6,3.98) B4(1.2,4.68) B5(0.8,3.98) B6(0.4,4.68) B7(-0.4,4.68) B8(-0.8,3.98) B9(-1.2,4.68) B10(-1.6,3.98) B11(-2.4,3.98) B12(-2.8,4.68)
  rrect100% 1x1.6 hole 1.2 slot 0.6 at 0 deg paste-2539.97 mask+0: 3(-4.27,3.53) 4(4.27,3.53) 6(-4.27,-1.2) 7(4.27,-1.2)
  rrect50% 0.2x1 smd paste+0 mask+0: 5(0,1.35) 8(0,-1.75)
  rrect33% 0.3x1.2 smd paste+0 mask+0: A1(-2.75,5.93) A2(-2.25,5.93) A3(-1.75,5.93) A4(-1.25,5.93) A5(-0.75,5.93) A6(-0.25,5.93) A7(0.25,5.93) A8(0.75,5.93) A9(1.25,5.93) A10(1.75,5.93) A11(2.25,5.93) A12(2.75,5.93)
  silkscreen extent -4.87,-0.03 4.87,7.28, body extent -4.87,-5.77 4.87,6.63, height 0.25
FP-885012104005_0201-IPC_C [mil]
  rrect38% 13.94x10.34 smd paste+0 mask+0: 1(-10.01,0) 2(10.01,0)
  body extent -12,-6 12,6, height 13
FP-885012104005_0201-MFG [mm]
  rrect48% 0.21x0.3 smd paste+0 mask+0: 1(-0.22,0) 2(0.22,0)
  body extent -0.3,-0.15 0.3,0.15, height 0.33
FP-885012106012_0603-IPC_C [mil]
  rrect12% 31.84x31.97 smd paste+0 mask+0: 1(-23.69,0) 2(23.69,0)
  body extent -44,-22 44,22, height 10
FP-885012106031_0603-IPC_C [mil]
  rrect11% 37.58x35.68 smd paste+0 mask+0: 1(-22.67,0) 2(22.67,0)
  body extent -45,-24 45,24, height 10
FP-885012205086_0402-IPC_A [mil]
  rrect12% 31.73x31.74 smd paste+0 mask+0: 1(-19.69,0) 2(19.69,0)
  silkscreen extent -36,-32 36,32, body extent -43,-24 43,24, height 10
FP-885012205086_0402-IPC_C [mil]
  rrect17% 23.85x23.87 smd paste+0 mask+0: 1(-15.76,0) 2(15.76,0)
  silkscreen extent -28,-30 28,30, body extent -32,-18 32,18, height 10
FP-885012205086_0402-MFG [mm]
  rrect20% 0.5x0.5 smd paste+0 mask+0: 1(-0.5,0) 2(0.5,0)
  body extent -0.5,-0.25 0.5,0.25, height 0.7
FP-885012208094_1206-MFG [mm]
  rrect11% 0.9x1.6 smd paste+0 mask+0: 1(-1.55,0) 2(1.55,0)
  silkscreen extent -0.72,-0.95 0.72,0.95, body extent -1.6,-0.8 1.6,0.8, height 1.9
FP-885012209048_1210-IPC_C [mil]
  rrect7% 53.28x102.61 smd paste+0 mask+0: 1(-48.25,0) 2(48.25,0)
  silkscreen extent -10,-53 10,53, body extent -79,-57 79,57, height 10
FP-885012209074_1210-IPC_C [mil]
  rrect7% 53.28x102.61 smd paste+0 mask+0: 1(-48.25,0) 2(48.25,0)
  silkscreen extent -10,-53 10,53, body extent -79,-57 79,57, height 10
FP-APS12808L-OBMX-BA_BGA24-IPC_C [mm]
  round 0.34 smd paste+0 mask+0: A2(-1,2) A3(0,2) A4(1,2) A5(2,2) B1(-2,1) B2(-1,1) B3(0,1) B4(1,1) B5(2,1) C1(-2,0) C2(-1,0) C3(0,0) C4(1,0) C5(2,0) D1(-2,-1) D2(-1,-1) D3(0,-1) D4(1,-1) D5(2,-1) E1(-2,-2) E2(-1,-2) E3(0,-2) E4(1,-2) E5(2,-2)
  silkscreen extent -3.6,-4 3,4, body extent -3.1,-4.1 3.1,4.1, height 0.25
FP-BC847BFA-7B_DFN3-MFG [mm]
  rrect50% 0.2x0.375 smd paste+0 mask+0: 1(-0.175,-0.312) 2(0.175,-0.312)
  rrect22% 0.45x0.475 smd paste+0 mask+0: 3(0,0.262)
  silkscreen extent -0.65,-0.43 0.65,0.43, body extent -0.43,-0.6 0.43,0.6, height 0.25
FP-CAT24M01HU5I-GT3_UDFN8-IPC_A [mm]
  rrect41% 1.008x0.242 smd paste+0 mask+0: 1(-1.475,0.75)
  rrect100% 1.008x0.242 smd paste+0 mask+0: 2(-1.475,0.25) 3(-1.475,-0.25) 4(-1.475,-0.75) 5(1.475,-0.75) 6(1.475,-0.25) 7(1.475,0.25) 8(1.475,0.75)
  rrect11% 0.95x1.45 smd paste-1000 mask+0: 9(0,0)
  silkscreen extent -2.9,-1.25 1.5,1.25, body extent -1.5,-1 1.5,1, height 0.55
FP-CRCW04020000Z0EDC_0402-IPC_C [mil]
  rrect21% 22.03x18.6 smd paste+0 mask+0: 1(-14.81,0) 2(14.81,0)
  body extent -30,-15 30,15, height 10
FP-GRM155R61A106ME18D_0402-IPC_C [mil]
  rrect16% 24.73x23.87 smd paste+0 mask+0: 1(-15.31,0) 2(15.31,0)
  body extent -32,-18 32,18, height 10
FP-GRM155R61A106ME18D_0402-MFG [mm]
  rrect22% 0.45x0.6 smd paste+0 mask+0: 1(-0.475,0) 2(0.475,0)
  body extent -0.8,-0.45 0.8,0.45, height 0.25
FP-MX25UW6445GXDQ00_BGA24-IPC_C [mm]
  round 0.34 smd paste+0 mask+0: A2(-1,2) A3(0,2) A4(1,2) A5(2,2) B1(-2,1) B2(-1,1) B3(0,1) B4(1,1) B5(2,1) C1(-2,0) C2(-1,0) C3(0,0) C4(1,0) C5(2,0) D1(-2,-1) D2(-1,-1) D3(0,-1) D4(1,-1) D5(2,-1) E1(-2,-2) E2(-1,-2) E3(0,-2) E4(1,-2) E5(2,-2)
  silkscreen extent -3.7,-4 3,4, body extent -3.1,-4.1 3.1,4.1, height 0.25
Keystone5011 [mil] "Keystone Multipurpose loops"
  round 87 hole 63: 1(0,0)
  silkscreen extent -70,-70 70,70, body extent -63,-63 63,62, height 319
Label_650x200 [mil] "Thermal Transfer Label"
  round 1 on Mech13: 0(0,0)
  silkscreen extent -325,-100 325,100, body extent -325,-100 325,100, height 1
Molex_693071010811 [mm] "MicroSD Card Connector, R/A, SMT"
  rrect12% 0.8x1.5 smd: 1(-1.942,3.1) 2(-0.842,2.7) 3(0.258,3.1) 4(1.358,3.3) 5(2.458,3.1) 6(3.558,3.3) 7(4.658,3.1) 8(5.758,3.1)
  rrect7% 1.4x1.9 smd: 9(-6.602,6.95) 9(6.548,5.95)
  rrect7% 1.8x1.4 smd: 10(-0.752,-7.2) 10(4.948,-7.2)
  silkscreen extent -6.99,-7.6 7.01,7.6, body extent -7,-7.6 7,7.6, height 1.83
NDK_NX3225GA [mm] "NDK"
  rect 1.2x1.4 smd: 1(-0.8,1.1) 2(-0.8,-1.1) 3(0.8,-1.1) 4(0.8,1.1)
  silkscreen extent -1.9,-0.1 1.4,2, body extent -1.3,-1.65 1.3,1.65, height 0.9
NKG0010A-MFG [mm]
  rrect50% 0.7x0.2 smd paste+0 mask+0: 1(-0.55,0.2) 2(-0.55,-0.2) 6(0.55,-0.2) 7(0.55,0.2)
  rrect50% 0.2x0.6 smd paste+0 mask+0: 3(-0.4,-0.8) 4(0,-0.8) 5(0.4,-0.8) 8(0.4,0.8) 9(0,0.8) 10(-0.4,0.8)
  silkscreen extent -1.55,-1.12 0.92,1.12, body extent -0.7,-0.9 0.7,0.9, height 0.55
NPTH125mil [mil]
  round 120 hole 125 unplated mask+15: 1(0,0)
"NY PMS 440 0025 PH" [mm] "4-40 nylon screw and mounting hole"
  round 8 hole 3.2: 1(0,0)
  body extent -3.3,-3.3 3.3,3.3, height 2.69
Panasonic_SMT_630x580 [mm] "SMD, 2-Leads, Dia 6.3mm"
  rrect6% 3.2x1.6 smd: 1(-2.5,0) 2(2.5,0)
  silkscreen extent -3.4,-3.4 3.4,3.4, body extent -3.4,-3.4 3.4,3.4, height 6.11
